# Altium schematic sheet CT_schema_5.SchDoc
size 334 x 183 mm
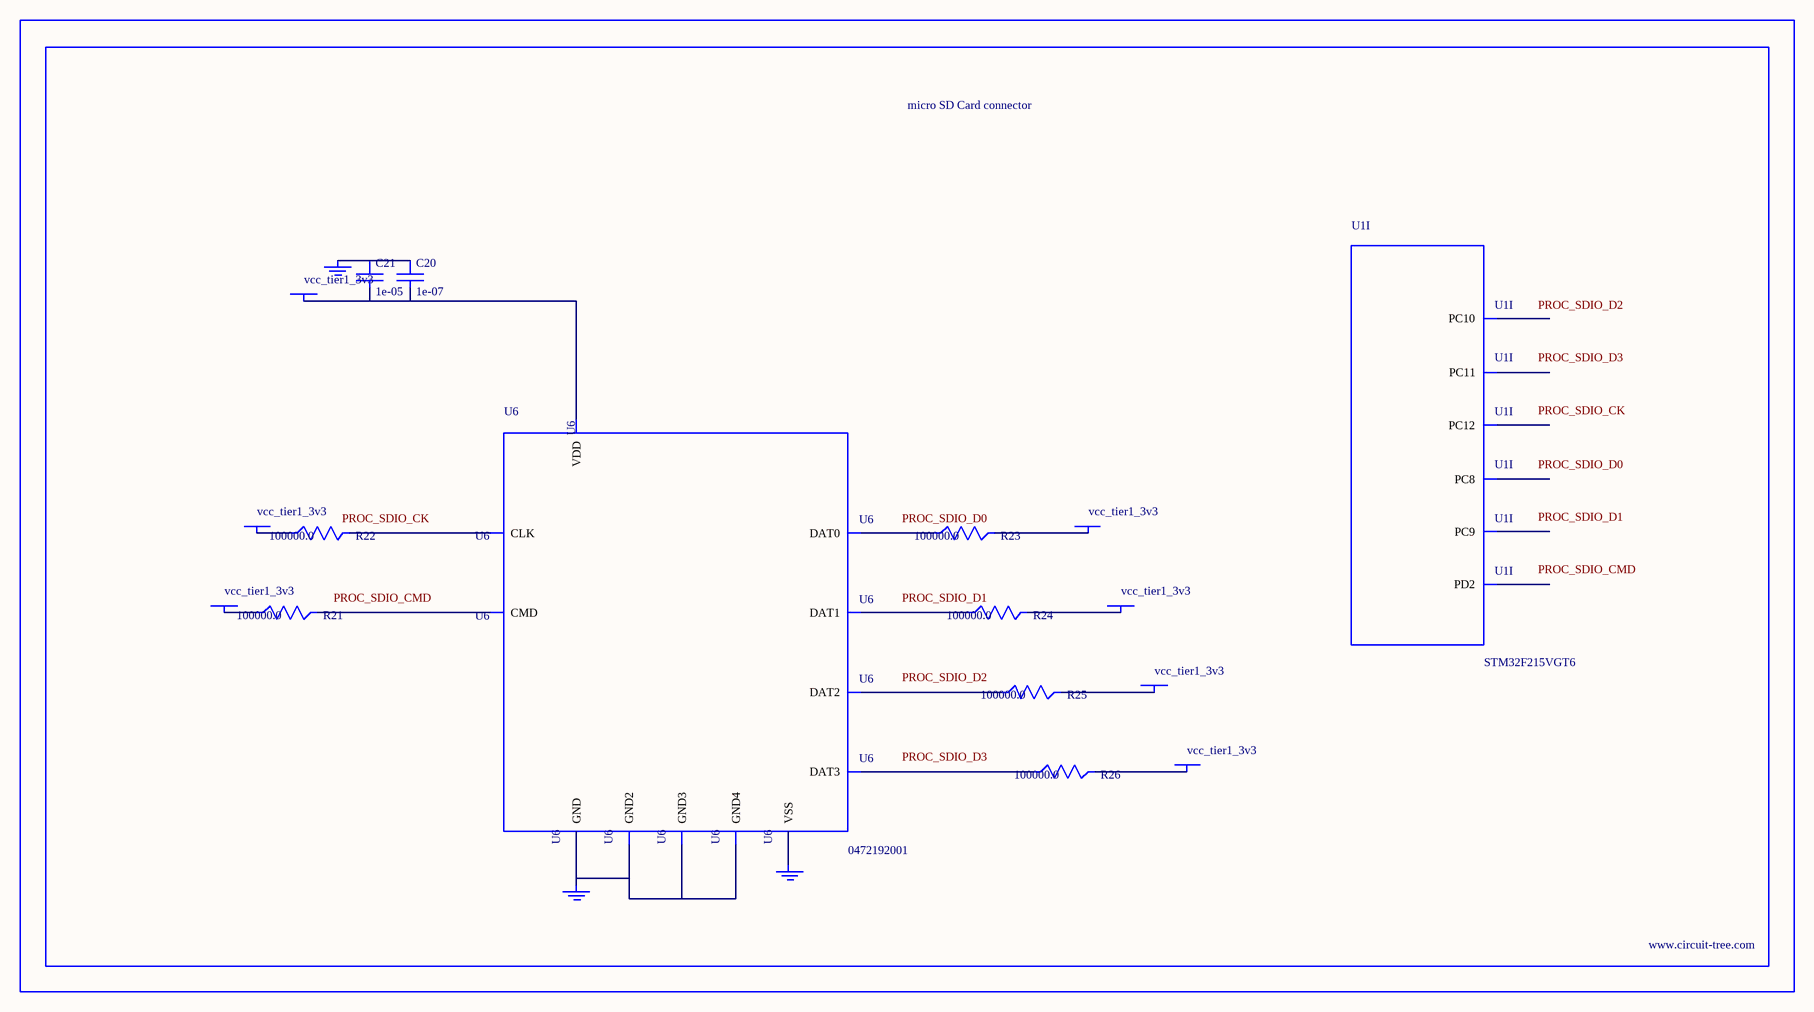
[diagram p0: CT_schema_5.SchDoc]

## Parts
BORDER4  (no value)
C20  1e-07  [C0402]
C21  1e-05  [C0805]
GND_INSTANCE_4_0  (no value)
GND_INSTANCE_4_1  (no value)
GND_INSTANCE_4_2  (no value)
POWER_INSTANCE_4_0  vcc_tier1_3v3
POWER_INSTANCE_4_1  vcc_tier1_3v3
POWER_INSTANCE_4_2  vcc_tier1_3v3
POWER_INSTANCE_4_3  vcc_tier1_3v3
POWER_INSTANCE_4_4  vcc_tier1_3v3
POWER_INSTANCE_4_5  vcc_tier1_3v3
POWER_INSTANCE_4_6  vcc_tier1_3v3
R21  100000.0  [R0603]
R22  100000.0  [R0603]
R23  100000.0  [R0603]
R24  100000.0  [R0603]
R25  100000.0  [R0603]
R26  100000.0  [R0603]
U1  STM32F215VGT6  [LQFP100]  (part I of 10)
U6  0472192001  [MOLEX_47219-2001]

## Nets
NetC20_1: C20.1 C21.1 GND_INSTANCE_4_0.0(GND)
NetC20_2: C20.2 C21.2 POWER_INSTANCE_4_3.0(PWR) U6.4(VDD)
NetGND_INSTANCE_4_1_0: GND_INSTANCE_4_1.0(GND) U6.6(VSS)
NetGND_INSTANCE_4_2_0: GND_INSTANCE_4_2.0(GND) U6.G1(GND) U6.G2(GND2) U6.G3(GND3) U6.G4(GND4)
NetPOWER_INSTANCE_4_0_0: POWER_INSTANCE_4_0.0(PWR) R25.2
NetPOWER_INSTANCE_4_1_0: POWER_INSTANCE_4_1.0(PWR) R26.2
NetPOWER_INSTANCE_4_2_0: POWER_INSTANCE_4_2.0(PWR) R21.1
NetPOWER_INSTANCE_4_4_0: POWER_INSTANCE_4_4.0(PWR) R22.1
NetPOWER_INSTANCE_4_5_0: POWER_INSTANCE_4_5.0(PWR) R23.2
NetPOWER_INSTANCE_4_6_0: POWER_INSTANCE_4_6.0(PWR) R24.2
NetR21_2: R21.2 U6.3(CMD)
NetR22_2: R22.2 U6.5(CLK)
NetR23_1: R23.1 U6.7(DAT0)
NetR24_1: R24.1 U6.8(DAT1)
NetR25_1: R25.1 U6.1(DAT2)
NetR26_1: R26.1 U6.2(DAT3)

Not connected (* = marked no-connect by the designer): U1 65(PC8) 66(PC9) 78(PC10) 79(PC11) 80(PC12) 83(PD2)

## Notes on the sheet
- Labels drawn without touching a wire or pin: PROC_SDIO_CK, PROC_SDIO_CMD, PROC_SDIO_D0, PROC_SDIO_D1, PROC_SDIO_D2, PROC_SDIO_D3

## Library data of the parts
BORDER4 = BORDER_PAGE4
C20 = C0402C104K3RACTU
C21 = C0805C106K8RACTU
GND_INSTANCE_4_0-GND_INSTANCE_4_2 = GND
POWER_INSTANCE_4_0-POWER_INSTANCE_4_6 = PWR
R21-R26 = RC0603JR-07100KL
